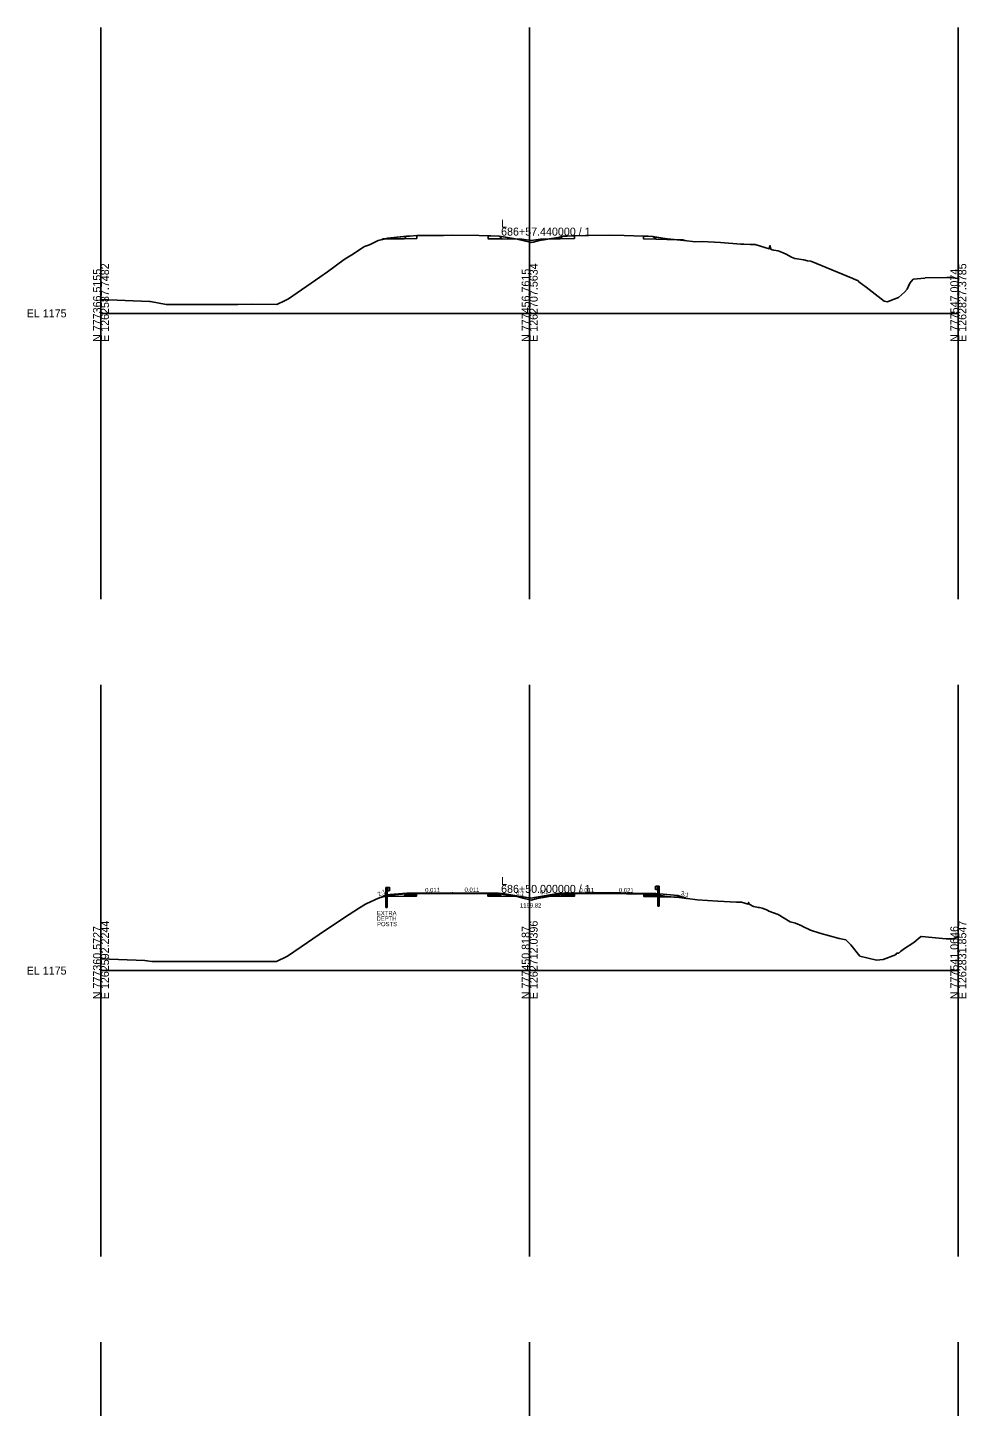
# Model space of a CAD drawing. Extents: x -41 to 1262860, y -100 to 777489.
# Drawn here: x 974.3 to 1302.8, y 1597.5 to 2080 of the extents above; entities that cross this region are included whole.
import ezdxf

# ---------------------------------------------------------------- set-up
doc = ezdxf.new("R2010")
doc.units = 0
for name, color, linetype in [('Exist Cross Section Cell', 7, 'Continuous'), ('Exist XS Center Line Elevation Label', 7, 'Continuous'), ('Exist XS Ground Line', 7, 'Continuous'), ('Prop CMT Guardrail Graphics', 7, 'Continuous'), ('Prop CMT Pvmt Course 1', 7, 'Continuous'), ('Prop CMT Pvmt Surface', 7, 'Continuous'), ('Prop CMT Shld Paved Course 1', 7, 'Continuous'), ('Prop CMT Shld Paved Course 2', 7, 'Continuous'), ('Prop CMT Shld Paved Course 4', 7, 'Continuous'), ('Prop CMT Subgrade Earthwork', 7, 'Continuous'), ('Prop XS Earthwork Shape', 7, 'Continuous'), ('Prop XS Exc Vertical Line 1', 7, 'Continuous'), ('Prop XS Exc Vertical Line 2', 7, 'Continuous'), ('Prop XS Exc Vertical Line 3', 7, 'Continuous'), ('Prop XS Finish Grade', 7, 'Continuous'), ('Prop XS SE Text', 7, 'Continuous'), ('Prop XS Side Slope Text', 7, 'Continuous'), ('Scratch_Level_4', 7, 'Continuous'), ('Scratch_Level_6', 7, 'Continuous')]:
    doc.layers.add(name, color=color, linetype=linetype)

msp = doc.modelspace()

# ---------------------------------------------------------------- linework, layer by layer
at = {"layer": 'Exist Cross Section Cell'}
for p, q in [((1150, 1980), (1150, 2010)), ((1000, 1980), (1150, 1980)), ((1150, 1980), (1300, 1980)), ((1150, 1750), (1150, 1780)), ((1000, 1750), (1150, 1750)), ((1150, 1750), (1300, 1750))]:
    msp.add_line(p, q, dxfattribs=at)
at = {"layer": 'Exist XS Ground Line'}
for points in [[(1000, 1984.82), (1016.95, 1984.14), (1017.31, 1984.11), (1022.81, 1983.11), (1046.97, 1983.1), (1047.9, 1983.1), (1053.16, 1983.22), (1061.52, 1983.12), (1064.45, 1984.54), (1065.65, 1985.09), (1076.55, 1992.71), (1079.24, 1994.58), (1085.14, 1998.79), (1086.03, 1999.39), (1087.76, 2000.53), (1091.83, 2003.18), (1092.26, 2003.39), (1093.94, 2003.99), (1097.03, 2005.45), (1100.3, 2006.32), (1100.32, 2006.33), (1100.35, 2006.33), (1107.11, 2006.99), (1108.04, 2007.05), (1110.54, 2007.21), (1119.81, 2007.29), (1123.15, 2007.32), (1132.35, 2007.21), (1135.45, 2007.17), (1136.4, 2007.13), (1139.23, 2006.98), (1139.24, 2006.98), (1144.38, 2006.19), (1145.68, 2006), (1150.06, 2004.86), (1150.51, 2004.75), (1151.27, 2004.93), (1153.5, 2005.47), (1155.02, 2005.7), (1159.96, 2006.59), (1161.74, 2006.97), (1163.18, 2007.05), (1165.64, 2007.18), (1170.61, 2007.25), (1177.79, 2007.35), (1183.13, 2007.22), (1189.84, 2007.06), (1191.5, 2006.95), (1193.15, 2006.85), (1196.59, 2006.33), (1198.18, 2006.09), (1203.97, 2005.5), (1207.99, 2005.04), (1210.32, 2005.09), (1216.84, 2004.77), (1223.9, 2004.25), (1225, 2004.19), (1227.17, 2004.13), (1228.87, 2004.07), (1230.74, 2003.51), (1233.79, 2002.55), (1234.09, 2003.74), (1234.43, 2002.41), (1234.88, 2002.19), (1235.4, 2002.08), (1236.99, 2001.83), (1238.75, 2001.12), (1238.96, 2001.09), (1239.71, 2000.66), (1241.66, 1999.69), (1242.76, 1999.15), (1245.93, 1998.67), (1247.2, 1998.35), (1248.44, 1998.21), (1250.39, 1997.45), (1263.05, 1992.22), (1264.34, 1991.64), (1264.55, 1991.57), (1264.78, 1991.51), (1264.85, 1991.49), (1264.91, 1991.43), (1265.22, 1991.03), (1267.78, 1989.2), (1274.08, 1984.3), (1275.2, 1984.03), (1276, 1984.37), (1279.09, 1985.53), (1280.14, 1986.52), (1281.19, 1987.47), (1282.08, 1988.45), (1282.98, 1990.58), (1284.23, 1991.92), (1288.33, 1992.34), (1288.43, 1992.42), (1296.04, 1992.57), (1297.06, 1992.49), (1299.8, 1992.23), (1300, 1992.23)], [(1000, 1754.15), (1015.32, 1753.53), (1016.06, 1753.48), (1017.84, 1753.15), (1059.3, 1753.14), (1060.9, 1753.14), (1061.08, 1753.14), (1061.38, 1753.14), (1065.04, 1754.91), (1065.28, 1755.03), (1069.99, 1758.31), (1076.38, 1762.64), (1080.27, 1765.31), (1086.81, 1769.69), (1090.5, 1772), (1092.58, 1773.25), (1093.05, 1773.47), (1097.1, 1775.39), (1099.01, 1775.9), (1100.38, 1776.27), (1106.62, 1776.86), (1106.67, 1776.87), (1107.12, 1776.92), (1107.18, 1776.92), (1110.53, 1777.13), (1122.93, 1777.24), (1123.15, 1777.24), (1135.06, 1777.09), (1135.45, 1777.07), (1135.86, 1777.06), (1139.23, 1776.89), (1139.24, 1776.89), (1139.36, 1776.87), (1145.69, 1775.92), (1147.65, 1775.41), (1150.5, 1774.69), (1152.25, 1775.11), (1153.37, 1775.39), (1154.88, 1775.64), (1161.1, 1776.78), (1161.71, 1776.89), (1165.45, 1777.09), (1165.62, 1777.1), (1177.72, 1777.26), (1177.83, 1777.26), (1181.17, 1777.18), (1189.83, 1776.97), (1189.97, 1776.96), (1193.1, 1776.77), (1194.02, 1776.63), (1198.04, 1775.98), (1202.31, 1775.59), (1205.26, 1775.26), (1208.61, 1774.8), (1215.87, 1774.28), (1222.43, 1773.92), (1222.88, 1773.9), (1223.24, 1773.91), (1224.19, 1773.99), (1226.47, 1773.27), (1226.62, 1773.85), (1226.79, 1773.2), (1228.29, 1772.47), (1230.07, 1772.08), (1230.44, 1772.03), (1231.33, 1771.83), (1233.24, 1771.14), (1233.75, 1770.82), (1237.02, 1769.59), (1241.18, 1767.11), (1243.05, 1766.64), (1245.23, 1765.64), (1245.28, 1765.61), (1245.34, 1765.59), (1248.33, 1764.19), (1251.55, 1763.15), (1258.34, 1761.29), (1260.66, 1760.75), (1262.43, 1759), (1265.55, 1755.02), (1271.32, 1753.66), (1273.71, 1753.91), (1277.99, 1755.58), (1278.43, 1756.05), (1279.17, 1756.09), (1279.78, 1756.68), (1281.17, 1757.73), (1284.07, 1759.59), (1284.4, 1759.81), (1286.71, 1761.73), (1286.73, 1761.76), (1286.74, 1761.77), (1286.76, 1761.78), (1286.97, 1761.93), (1287.1, 1761.94), (1287.12, 1761.94), (1295.72, 1761.11), (1298.21, 1761.12), (1300, 1761.97)]]:
    msp.add_lwpolyline(points, dxfattribs=at)
at = {"layer": 'Prop CMT Guardrail Graphics'}
for p, q in [((1099.7, 1779.13), (1100.19, 1779.13)), ((1099.7, 1776.63), (1099.7, 1779.13)), ((1099.7, 1772.12), (1099.7, 1776.63)), ((1100.19, 1777.95), (1100.19, 1779.13)), ((1100.19, 1779.13), (1100.86, 1779.13)), ((1100.19, 1779.13), (1100.19, 1776.62)), ((1100.86, 1777.95), (1100.19, 1777.95)), ((1100.19, 1776.62), (1100.19, 1772.12)), ((1100.86, 1779.13), (1100.86, 1777.95)), ((1100.86, 1779.05), (1100.86, 1778.03)), ((1100.95, 1779.03), (1100.86, 1779.05)), ((1100.86, 1778.03), (1100.95, 1778.05)), ((1100.87, 1778.58), (1101.1, 1778.79)), ((1100.87, 1778.49), (1100.87, 1778.58)), ((1101.1, 1778.29), (1100.87, 1778.49)), ((1101.1, 1778.93), (1100.95, 1779.03)), ((1100.95, 1778.05), (1101.1, 1778.15)), ((1101.1, 1778.79), (1101.1, 1778.93)), ((1101.1, 1778.15), (1101.1, 1778.29)), ((1193.96, 1779.34), (1194.1, 1779.44)), ((1193.96, 1779.2), (1193.96, 1779.34)), ((1194.19, 1779), (1193.96, 1779.2)), ((1193.96, 1778.7), (1194.19, 1778.91)), ((1193.96, 1778.56), (1193.96, 1778.7)), ((1194.1, 1778.46), (1193.96, 1778.56)), ((1194.1, 1779.44), (1194.2, 1779.46)), ((1194.2, 1778.44), (1194.1, 1778.46)), ((1194.19, 1778.91), (1194.19, 1779)), ((1194.2, 1779.54), (1194.2, 1778.36)), ((1194.87, 1779.54), (1194.2, 1779.54)), ((1194.2, 1779.46), (1194.2, 1778.44)), ((1194.2, 1778.36), (1194.87, 1778.36)), ((1195.35, 1779.54), (1194.87, 1779.54)), ((1194.87, 1778.36), (1194.87, 1779.54)), ((1194.87, 1779.54), (1194.87, 1777.03)), ((1194.87, 1777.03), (1194.87, 1772.53)), ((1195.35, 1777.04), (1195.35, 1779.54)), ((1195.35, 1772.53), (1195.35, 1777.04)), ((1100.19, 1772.12), (1099.7, 1772.12)), ((1194.87, 1772.53), (1195.35, 1772.53))]:
    msp.add_line(p, q, dxfattribs=at)
at = {"layer": 'Prop CMT Pvmt Course 1'}
msp.add_line((1135.33, 1776.88), (1139.38, 1776.83), dxfattribs=at)
for points in [[(1110.46, 1777.13), (1110.46, 1776.88), (1122.89, 1777.01), (1122.89, 1777.01), (1135.33, 1776.88), (1135.33, 1776.88), (1135.33, 1777.01), (1135.33, 1777.01), (1135.33, 1777.13), (1122.89, 1777.26), (1122.89, 1777.26), (1110.46, 1777.13), (1110.89, 1777.13)], [(1189.91, 1777.03), (1177.81, 1777.28), (1177.81, 1777.28), (1165.72, 1777.15), (1165.72, 1777.01), (1165.72, 1777.01), (1165.72, 1777.01), (1165.72, 1776.9), (1177.81, 1777.03), (1177.81, 1777.03), (1189.91, 1776.78)]]:
    msp.add_lwpolyline(points, dxfattribs=at)
at = {"layer": 'Prop CMT Pvmt Surface'}
for p, q in [((1107, 1777.09), (1110.46, 1777.13)), ((1122.89, 1777.26), (1110.46, 1777.13)), ((1135.33, 1777.13), (1122.89, 1777.26)), ((1135.33, 1777.13), (1139.13, 1777.08)), ((1165.72, 1777.15), (1161.81, 1777.11)), ((1165.72, 1777.15), (1177.81, 1777.28)), ((1189.91, 1777.03), (1177.81, 1777.28)), ((1194.15, 1776.94), (1189.91, 1777.03))]:
    msp.add_line(p, q, dxfattribs=at)
at = {"layer": 'Prop CMT Shld Paved Course 1'}
for p, q in [((1135.33, 1777.13), (1135.33, 1776.88)), ((1139.38, 1776.83), (1139.13, 1777.08)), ((1161.81, 1777.11), (1161.56, 1776.85)), ((1165.72, 1776.9), (1161.56, 1776.85)), ((1165.71, 1777.15), (1165.71, 1777.15)), ((1165.71, 1777.15), (1165.71, 1777.15)), ((1165.72, 1777.15), (1165.72, 1776.9)), ((1165.72, 1777.15), (1165.72, 1777.15)), ((1189.91, 1777.03), (1189.91, 1777.03)), ((1189.91, 1777.03), (1189.91, 1777.03)), ((1189.91, 1777.03), (1189.91, 1776.78)), ((1189.91, 1776.78), (1194.4, 1776.68)), ((1194.15, 1776.94), (1194.4, 1776.68))]:
    msp.add_line(p, q, dxfattribs=at)
msp.add_lwpolyline([(1107, 1777.09), (1110.46, 1777.13), (1110.46, 1777.13), (1110.46, 1776.88), (1106.75, 1776.84), (1106.75, 1776.84), (1106.75, 1776.84), (1107, 1777.09), (1107, 1777.09)], dxfattribs=at)
at = {"layer": 'Prop CMT Shld Paved Course 2'}
for p, q in [((1135.33, 1776.88), (1135.33, 1776.54)), ((1135.33, 1776.54), (1139.72, 1776.49)), ((1139.72, 1776.49), (1139.38, 1776.83)), ((1161.22, 1776.52), (1161.56, 1776.85)), ((1161.22, 1776.52), (1165.72, 1776.57)), ((1165.72, 1776.9), (1165.72, 1776.57)), ((1189.91, 1776.78), (1189.91, 1776.44)), ((1189.91, 1776.44), (1194.74, 1776.34)), ((1194.4, 1776.68), (1194.74, 1776.34))]:
    msp.add_line(p, q, dxfattribs=at)
msp.add_lwpolyline([(1106.75, 1776.84), (1110.46, 1776.88), (1110.46, 1776.88), (1110.46, 1776.55), (1106.41, 1776.5), (1106.41, 1776.5), (1106.41, 1776.5), (1106.75, 1776.84), (1106.75, 1776.84)], dxfattribs=at)
at = {"layer": 'Prop CMT Shld Paved Course 4'}
for p, q in [((1135.33, 1776.54), (1135.33, 1776.08)), ((1135.33, 1776.08), (1140.18, 1776.03)), ((1140.18, 1776.03), (1139.72, 1776.49)), ((1160.76, 1776.05), (1161.22, 1776.52)), ((1160.76, 1776.05), (1165.72, 1776.11)), ((1165.72, 1776.57), (1165.72, 1776.11)), ((1189.91, 1776.44), (1189.91, 1775.99)), ((1189.91, 1775.99), (1203.78, 1775.69)), ((1194.74, 1776.34), (1195.21, 1775.87))]:
    msp.add_line(p, q, dxfattribs=at)
msp.add_lwpolyline([(1106.41, 1776.5), (1110.46, 1776.55), (1110.46, 1776.55), (1110.46, 1776.09), (1105.95, 1776.04), (1105.95, 1776.04), (1105.95, 1776.04), (1106.41, 1776.5), (1106.41, 1776.5), (1106.41, 1776.5), (1106.41, 1776.5)], dxfattribs=at)
at = {"layer": 'Prop CMT Subgrade Earthwork'}
for p, q in [((1110.46, 1776.09), (1098.61, 1775.96)), ((1110.46, 1777.13), (1110.46, 1776.09)), ((1135.33, 1777.08), (1135.33, 1776.08)), ((1135.33, 1776.08), (1147.05, 1775.95)), ((1153.95, 1775.98), (1165.72, 1776.11)), ((1165.72, 1777.1), (1165.72, 1776.11)), ((1189.91, 1775.99), (1189.91, 1776.96)), ((1189.91, 1775.99), (1203.78, 1775.69))]:
    msp.add_line(p, q, dxfattribs=at)
at = {"layer": 'Prop XS Earthwork Shape'}
for points in [[(1110.54, 2006.17), (1110.54, 2007.21), (1108.04, 2007.05), (1107.11, 2006.99), (1106.9, 2006.97), (1106.06, 2006.13)], [(1098.78, 2006.06), (1098.17, 2005.75), (1099.34, 2006.07)], [(1100.35, 2006.33), (1106.9, 2006.97), (1106.06, 2006.13), (1099.34, 2006.07), (1100.3, 2006.32), (1100.32, 2006.33)], [(1136.4, 2007.13), (1139.23, 2006.98), (1139.42, 2006.95), (1140.3, 2006.07), (1135.45, 2006.13), (1135.45, 2007.17)], [(1139.42, 2006.95), (1144.38, 2006.19), (1145.6, 2006.01), (1140.3, 2006.07)], [(1153.78, 2005.99), (1156.86, 2006.03), (1155.02, 2005.7), (1153.5, 2005.47), (1151.27, 2004.93), (1150.51, 2004.75), (1150.06, 2004.86), (1145.68, 2006), (1145.6, 2006.01), (1147.21, 2005.99), (1150.5, 2005.44)], [(1159.96, 2006.59), (1161.54, 2006.93), (1160.68, 2006.08), (1156.86, 2006.03)], [(1165.64, 2006.14), (1165.64, 2007.18), (1163.18, 2007.05), (1161.74, 2006.97), (1161.54, 2006.93), (1160.68, 2006.08)], [(1193.3, 2006.83), (1194.22, 2005.91), (1189.84, 2006.02), (1189.84, 2007.06), (1191.5, 2006.95), (1193.15, 2006.85)], [(1198.18, 2006.09), (1201.57, 2005.74), (1194.22, 2005.91), (1193.3, 2006.83), (1196.59, 2006.33)], [(1203.61, 2005.7), (1204.32, 2005.46), (1203.97, 2005.5), (1201.57, 2005.74)], [(1099.01, 1775.9), (1099.26, 1775.97), (1098.61, 1775.96), (1097.87, 1775.59)], [(1106.62, 1776.86), (1106.67, 1776.87), (1106.79, 1776.88), (1105.95, 1776.04), (1099.26, 1775.97), (1100.38, 1776.27)], [(1107.12, 1776.92), (1107.18, 1776.92), (1110.46, 1777.13), (1110.46, 1776.09), (1105.95, 1776.04), (1106.79, 1776.88)], [(1139.24, 1776.89), (1139.33, 1776.88), (1140.18, 1776.03), (1135.33, 1776.08), (1135.33, 1777.08), (1135.45, 1777.07), (1135.86, 1777.06), (1139.23, 1776.89)], [(1139.36, 1776.87), (1145.35, 1775.97), (1140.18, 1776.03), (1139.33, 1776.88)], [(1153.95, 1775.98), (1156.87, 1776.01), (1154.88, 1775.64), (1153.37, 1775.39), (1152.25, 1775.11), (1150.5, 1774.69), (1147.65, 1775.41), (1145.69, 1775.92), (1145.35, 1775.97), (1147.05, 1775.95), (1150.43, 1775.39)], [(1156.87, 1776.01), (1161.1, 1776.78), (1161.57, 1776.87), (1160.76, 1776.05)], [(1165.45, 1777.09), (1165.62, 1777.1), (1165.72, 1777.1), (1165.72, 1776.11), (1160.76, 1776.05), (1161.57, 1776.87), (1161.71, 1776.89)], [(1194.54, 1776.54), (1195.21, 1775.87), (1189.91, 1775.99), (1189.91, 1776.96), (1189.97, 1776.96), (1193.1, 1776.77), (1194.02, 1776.63)], [(1194.54, 1776.54), (1195.21, 1775.87), (1200.44, 1775.76), (1198.04, 1775.98)], [(1200.44, 1775.76), (1202.31, 1775.59), (1204.98, 1775.29), (1203.78, 1775.69)]]:
    msp.add_lwpolyline(points, close=True, dxfattribs=at)
at = {"layer": 'Prop XS Exc Vertical Line 1'}
for p, q in [((1000, 1880), (1000, 2080)), ((1000, 1650), (1000, 1850)), ((1000, 1420), (1000, 1620))]:
    msp.add_line(p, q, dxfattribs=at)
at = {"layer": 'Prop XS Exc Vertical Line 2'}
for p, q in [((1150, 1880), (1150, 2080)), ((1150, 1650), (1150, 1850)), ((1150, 1420), (1150, 1620))]:
    msp.add_line(p, q, dxfattribs=at)
at = {"layer": 'Prop XS Exc Vertical Line 3'}
for p, q in [((1300, 1880), (1300, 2080)), ((1300, 1650), (1300, 1850)), ((1300, 1420), (1300, 1620))]:
    msp.add_line(p, q, dxfattribs=at)
at = {"layer": 'Prop XS Finish Grade'}
for p, q in [((1099.7, 1776.51), (1097.87, 1775.59)), ((1099.7, 1776.51), (1107, 1777.09)), ((1107, 1777.09), (1105.95, 1776.04)), ((1139.13, 1777.08), (1141.33, 1776.91)), ((1139.13, 1777.08), (1140.18, 1776.03)), ((1141.33, 1776.91), (1150.43, 1775.39)), ((1159.72, 1776.94), (1150.43, 1775.39)), ((1159.72, 1776.94), (1161.81, 1777.11)), ((1161.81, 1777.11), (1160.76, 1776.05)), ((1194.15, 1776.94), (1201.91, 1776.32)), ((1194.15, 1776.94), (1195.21, 1775.87)), ((1201.91, 1776.32), (1204.98, 1775.29)), ((1150, 1775.43), (1150, 1775.43)), ((1150, 1775.43), (1150, 1775.43))]:
    msp.add_line(p, q, dxfattribs=at)
at = {"layer": 'Scratch_Level_4'}
for p, q in [((1300, 1880), (1300, 2080)), ((1300, 1650), (1300, 1850)), ((1300, 1420), (1300, 1620))]:
    msp.add_line(p, q, dxfattribs=at)
at = {"layer": 'Scratch_Level_6'}
for p, q in [((1000, 1880), (1000, 2080)), ((1000, 1650), (1000, 1850)), ((1000, 1420), (1000, 1620))]:
    msp.add_line(p, q, dxfattribs=at)

# ---------------------------------------------------------------- texts
at = {"layer": 'Exist Cross Section Cell'}
for s, p in [('L', (1140, 2010)), ('686+57.440000 / 1', (1140, 2007.2)), ('EL 1175', (974, 1978.6)), ('L', (1140, 1780)), ('686+50.000000 / 1', (1140, 1777.2)), ('EL 1175', (974, 1748.6))]:
    msp.add_text(s, height=2.8, dxfattribs=at).set_placement(p)
for s, p in [('N 777366.5155', (1000, 1970)), ('E 1262587.7482', (1002.8, 1970)), ('N 777456.7615', (1150, 1970)), ('E 1262707.5634', (1152.8, 1970)), ('N 777547.0074', (1300, 1970)), ('E 1262827.3785', (1302.8, 1970)), ('E 1262592.2244', (1002.8, 1740)), ('E 1262712.0396', (1152.8, 1740)), ('E 1262831.8547', (1302.8, 1740)), ('N 777360.5727', (1000, 1740)), ('N 777450.8187', (1150, 1740)), ('N 777541.0646', (1300, 1740))]:
    msp.add_text(s, height=2.8, rotation=90, dxfattribs=at).set_placement(p)
at = {"layer": 'Exist XS Center Line Elevation Label'}
msp.add_text('1199.82', height=1.5, dxfattribs=at).set_placement((1146.61, 1772.07))
at = {"layer": 'Prop XS SE Text'}
for s, rotation, p in [('0.011', 1.1458, (1113.45, 1777.4)), ('0.011', 359.8799, (1127.21, 1777.54)), ('0.011', 0.6501, (1167.41, 1777.39)), ('0.021', 358.8542, (1181.2, 1777.44))]:
    msp.add_text(s, height=1.5, rotation=rotation, dxfattribs=at).set_placement(p)
for s, p in [('EXTRA', (1096.53, 1769.36)), ('DEPTH', (1096.4, 1767.45)), ('POSTS', (1096.59, 1765.55))]:
    msp.add_text(s, height=1.5, dxfattribs=at).set_placement(p)
at = {"layer": 'Prop XS Side Slope Text'}
for s, rotation, p in [('2:1', 26.5651, (1097.23, 1775.92)), ('6:1', 350.5377, (1145.19, 1776.64)), ('6:1', 9.4623, (1153.76, 1776.63)), ('3:1', 341.5651, (1202.73, 1776.55))]:
    msp.add_text(s, height=1.5, rotation=rotation, dxfattribs=at).set_placement(p)

doc.saveas('drawing.dxf')
